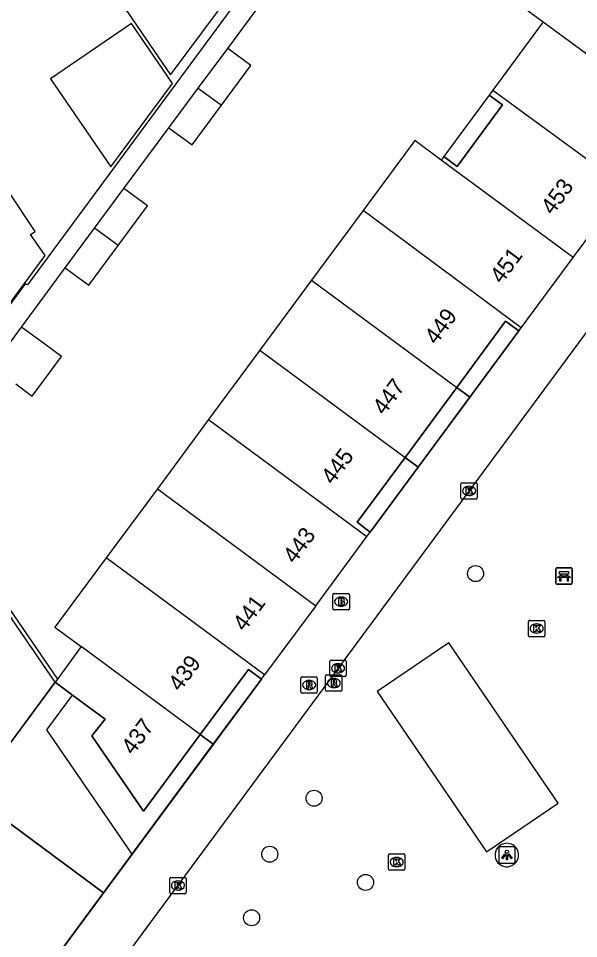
# Model space of a CAD drawing. Extents: x 155275 to 156263, y 382654 to 383635.
# Drawn here: x 155771.6 to 155805.7, y 383268.4 to 383324.6 of the extents above; entities that cross this region are included whole.
import ezdxf

# ---------------------------------------------------------------- set-up
doc = ezdxf.new("R2010")
doc.units = 0
for name, color, linetype in [('IMGEO_Bank', 7, 'Continuous'), ('IMGEO_Boom', 7, 'Continuous'), ('IMGEO_Brandkraan', 7, 'Continuous'), ('IMGEO_Kolk', 7, 'Continuous'), ('IMGEO_Lichtpunt', 7, 'Continuous'), ('IMGEO_Muur', 7, 'Continuous'), ('IMGEO_Pand', 7, 'Continuous'), ('IMGEO_Pand_nummerreeks', 7, 'Continuous'), ('IMGEO_Pand_overbouw', 7, 'Continuous'), ('IMGEO_Rijbaan_lokaal_open', 7, 'Continuous'), ('IMGEO_Rioolput', 7, 'Continuous'), ('IMGEO_Voetpad_open', 7, 'Continuous')]:
    doc.layers.add(name, color=color, linetype=linetype)

msp = doc.modelspace()

# ---------------------------------------------------------------- linework, layer by layer
at = {"layer": 'IMGEO_Bank'}
for p, q in [((155804.349, 383290.13), (155804.349, 383290.971)), ((155804.349, 383290.971), (155804.349, 383290.13)), ((155804.424, 383291.055), (155805.265, 383291.055)), ((155805.265, 383291.055), (155804.424, 383291.055)), ((155805.349, 383290.98), (155805.349, 383290.139)), ((155805.349, 383290.139), (155805.349, 383290.98)), ((155805.046, 383290.453), (155804.653, 383290.453)), ((155804.658, 383290.561), (155804.658, 383290.667)), ((155804.702, 383290.667), (155804.702, 383290.561)), ((155804.99, 383290.673), (155804.708, 383290.673)), ((155804.708, 383290.555), (155804.99, 383290.555)), ((155804.996, 383290.561), (155804.996, 383290.667)), ((155805.04, 383290.667), (155805.04, 383290.561)), ((155805.274, 383290.055), (155804.433, 383290.055)), ((155804.433, 383290.055), (155805.274, 383290.055))]:
    msp.add_line(p, q, dxfattribs=at)
for points in [[(155804.652, 383290.673), (155804.566, 383290.673), (155804.566, 383290.834), (155805.129, 383290.834), (155805.129, 383290.673), (155805.046, 383290.673)], [(155804.596, 383290.453), (155804.454, 383290.453), (155804.566, 383290.555), (155804.652, 383290.555)], [(155804.646, 383290.446), (155804.646, 383290.239), (155804.603, 383290.239), (155804.603, 383290.446)], [(155805.046, 383290.555), (155805.129, 383290.555), (155805.241, 383290.453), (155805.102, 383290.453)], [(155805.096, 383290.446), (155805.096, 383290.239), (155805.052, 383290.239), (155805.052, 383290.446)]]:
    msp.add_lwpolyline(points, dxfattribs=at)
for centre, radius, start, end in [((155804.427, 383290.977), 0.0779, 92.4484, 184.2845), ((155804.427, 383290.977), 0.0779, 92.4484, 184.2845), ((155805.271, 383290.977), 0.0779, 2.4484, 94.2845), ((155805.271, 383290.977), 0.0779, 2.4484, 94.2845), ((155804.596, 383290.446), 0.00671, 2.8957, 87.1043), ((155804.653, 383290.446), 0.00671, 92.8957, 177.1043), ((155804.651, 383290.666), 0.00671, 2.8957, 87.1043), ((155804.651, 383290.562), 0.00671, 272.8957, 357.1043), ((155804.708, 383290.666), 0.00671, 92.8957, 177.1043), ((155804.708, 383290.562), 0.00671, 182.8957, 267.1043), ((155804.99, 383290.666), 0.00671, 2.8957, 87.1043), ((155804.99, 383290.562), 0.00671, 272.8957, 357.1043), ((155805.047, 383290.666), 0.00671, 92.8957, 177.1043), ((155805.047, 383290.562), 0.00671, 182.8957, 267.1043), ((155805.045, 383290.446), 0.00671, 2.8957, 87.1043), ((155805.102, 383290.446), 0.00671, 92.8957, 177.1043), ((155804.427, 383290.133), 0.0779, 182.4484, 274.2845), ((155804.427, 383290.133), 0.0779, 182.4484, 274.2845), ((155805.271, 383290.133), 0.0779, 272.4484, 4.2845), ((155805.271, 383290.133), 0.0779, 272.4484, 4.2845)]:
    msp.add_arc(centre, radius, start, end, dxfattribs=at)
at = {"layer": 'IMGEO_Boom'}
for centre in [(155799.459, 383290.696), (155789.62, 383277), (155786.919, 383273.583), (155792.753, 383271.865), (155785.813, 383269.709)]:
    msp.add_circle(centre, 0.489, dxfattribs=at)
at = {"layer": 'IMGEO_Brandkraan'}
for p, q in [((155790.768, 383288.56), (155790.768, 383289.412)), ((155790.843, 383289.486), (155791.695, 383289.486)), ((155791.256, 383289.266), (155791.281, 383289.266)), ((155791.769, 383289.412), (155791.769, 383288.56)), ((155791.695, 383288.486), (155790.843, 383288.486)), ((155791.279, 383288.706), (155791.254, 383288.706))]:
    msp.add_line(p, q, dxfattribs=at)
for points in [[(155790.768, 383288.56), (155790.768, 383289.412)], [(155790.843, 383289.486), (155791.695, 383289.486)], [(155791.116, 383289.186), (155791.116, 383288.786), (155791.329, 383288.786)], [(155791.347, 383289.186), (155791.116, 383289.186)], [(155791.295, 383289.105), (155791.241, 383289.105), (155791.241, 383289.029)], [(155791.769, 383289.412), (155791.769, 383288.56)], [(155791.695, 383288.486), (155790.843, 383288.486)], [(155791.241, 383289.029), (155791.294, 383289.029)], [(155791.303, 383288.953), (155791.241, 383288.953), (155791.241, 383288.872)], [(155791.241, 383288.872), (155791.303, 383288.872)]]:
    msp.add_lwpolyline(points, dxfattribs=at)
for centre, radius, start, end in [((155790.845, 383289.41), 0.0765, 91.552, 178.448), ((155790.845, 383289.41), 0.0765, 91.552, 178.448), ((155791.296, 383289.067), 0.0379, 267.8285, 90.9355), ((155791.351, 383289.041), 0.145, 59.4692, 91.5367), ((155791.376, 383289.088), 0.0922, 285.5137, 58.1501), ((155791.693, 383289.41), 0.0765, 1.552, 88.448), ((155791.693, 383289.41), 0.0765, 1.552, 88.448), ((155790.845, 383288.562), 0.0765, 181.552, 268.448), ((155790.845, 383288.562), 0.0765, 181.552, 268.448), ((155791.304, 383288.912), 0.0404, 269.8759, 90.5077), ((155791.335, 383289.037), 0.251, 268.6676, 293.5347), ((155791.381, 383288.896), 0.105, 301.3115, 78.989), ((155791.693, 383288.562), 0.0765, 271.552, 358.448), ((155791.693, 383288.562), 0.0765, 271.552, 358.448)]:
    msp.add_arc(centre, radius, start, end, dxfattribs=at)
for centre, major_axis, ratio, start_param, end_param in [((155791.255, 383288.986), (-0.387, 0.002), 0.722429, 4.712389, 7.853982), ((155791.28, 383288.986), (-0.39, 0.002), 0.717154, 1.570796, 4.712389)]:
    msp.add_ellipse(centre, major_axis=major_axis, ratio=ratio, start_param=start_param, end_param=end_param, dxfattribs=at)
at = {"layer": 'IMGEO_Kolk'}
for p, q in [((155798.564, 383295.315), (155798.564, 383296.167)), ((155798.639, 383296.241), (155799.491, 383296.241)), ((155799.052, 383296.021), (155799.077, 383296.021)), ((155799.565, 383296.167), (155799.565, 383295.315)), ((155799.491, 383295.241), (155798.639, 383295.241)), ((155799.075, 383295.461), (155799.05, 383295.461)), ((155802.681, 383286.922), (155802.681, 383287.774)), ((155802.756, 383287.848), (155803.608, 383287.848)), ((155803.169, 383287.628), (155803.194, 383287.628)), ((155803.682, 383287.774), (155803.682, 383286.922)), ((155803.608, 383286.848), (155802.756, 383286.848)), ((155803.192, 383287.068), (155803.167, 383287.068)), ((155790.579, 383284.499), (155790.579, 383285.351)), ((155790.654, 383285.425), (155791.506, 383285.425)), ((155791.067, 383285.205), (155791.092, 383285.205)), ((155791.58, 383285.351), (155791.58, 383284.499)), ((155791.09, 383284.645), (155791.065, 383284.645)), ((155791.506, 383284.425), (155790.654, 383284.425)), ((155794.153, 383272.681), (155794.153, 383273.533)), ((155794.228, 383273.607), (155795.08, 383273.607)), ((155794.641, 383273.387), (155794.666, 383273.387)), ((155795.154, 383273.533), (155795.154, 383272.681)), ((155794.664, 383272.827), (155794.639, 383272.827)), ((155795.08, 383272.607), (155794.228, 383272.607)), ((155780.824, 383271.247), (155780.824, 383272.099)), ((155780.899, 383272.173), (155781.751, 383272.173)), ((155781.312, 383271.953), (155781.337, 383271.953)), ((155781.825, 383272.099), (155781.825, 383271.247)), ((155781.751, 383271.173), (155780.899, 383271.173)), ((155781.335, 383271.393), (155781.31, 383271.393))]:
    msp.add_line(p, q, dxfattribs=at)
for points in [[(155798.564, 383295.315), (155798.564, 383296.167)], [(155798.639, 383296.241), (155799.491, 383296.241)], [(155798.885, 383295.941), (155799.008, 383295.941), (155799.008, 383295.79), (155799.138, 383295.941), (155799.302, 383295.941), (155799.156, 383295.79), (155799.309, 383295.541), (155799.157, 383295.541), (155799.072, 383295.705), (155799.008, 383295.638), (155799.008, 383295.541), (155798.885, 383295.541), (155798.885, 383295.941)], [(155799.565, 383296.167), (155799.565, 383295.315)], [(155799.491, 383295.241), (155798.639, 383295.241)], [(155802.681, 383286.922), (155802.681, 383287.774)], [(155802.756, 383287.848), (155803.608, 383287.848)], [(155803.002, 383287.548), (155803.125, 383287.548), (155803.125, 383287.397), (155803.255, 383287.548), (155803.419, 383287.548), (155803.273, 383287.397), (155803.426, 383287.148), (155803.274, 383287.148), (155803.189, 383287.312), (155803.125, 383287.245), (155803.125, 383287.148), (155803.002, 383287.148), (155803.002, 383287.548)], [(155803.682, 383287.774), (155803.682, 383286.922)], [(155803.608, 383286.848), (155802.756, 383286.848)], [(155790.579, 383284.499), (155790.579, 383285.351)], [(155790.654, 383285.425), (155791.506, 383285.425)], [(155790.9, 383285.125), (155791.023, 383285.125), (155791.023, 383284.974), (155791.153, 383285.125), (155791.317, 383285.125), (155791.171, 383284.974), (155791.324, 383284.725), (155791.172, 383284.725), (155791.087, 383284.889), (155791.023, 383284.822), (155791.023, 383284.725), (155790.9, 383284.725), (155790.9, 383285.125)], [(155791.58, 383285.351), (155791.58, 383284.499)], [(155791.506, 383284.425), (155790.654, 383284.425)], [(155794.153, 383272.681), (155794.153, 383273.533)], [(155794.228, 383273.607), (155795.08, 383273.607)], [(155795.154, 383273.533), (155795.154, 383272.681)], [(155794.474, 383273.307), (155794.597, 383273.307), (155794.597, 383273.156), (155794.727, 383273.307), (155794.891, 383273.307), (155794.745, 383273.156), (155794.898, 383272.907), (155794.746, 383272.907), (155794.661, 383273.071), (155794.597, 383273.004), (155794.597, 383272.907), (155794.474, 383272.907), (155794.474, 383273.307)], [(155795.08, 383272.607), (155794.228, 383272.607)], [(155780.824, 383271.247), (155780.824, 383272.099)], [(155780.899, 383272.173), (155781.751, 383272.173)], [(155781.145, 383271.873), (155781.268, 383271.873), (155781.268, 383271.722), (155781.398, 383271.873), (155781.562, 383271.873), (155781.416, 383271.722), (155781.569, 383271.473), (155781.417, 383271.473), (155781.332, 383271.637), (155781.268, 383271.57), (155781.268, 383271.473), (155781.145, 383271.473), (155781.145, 383271.873)], [(155781.825, 383272.099), (155781.825, 383271.247)], [(155781.751, 383271.173), (155780.899, 383271.173)]]:
    msp.add_lwpolyline(points, dxfattribs=at)
for centre, start, end in [((155798.641, 383296.165), 91.552, 178.448), ((155798.641, 383296.165), 91.552, 178.448), ((155799.489, 383296.165), 1.552, 88.448), ((155799.489, 383296.165), 1.552, 88.448), ((155798.641, 383295.317), 181.552, 268.448), ((155798.641, 383295.317), 181.552, 268.448), ((155799.489, 383295.317), 271.552, 358.448), ((155799.489, 383295.317), 271.552, 358.448), ((155802.758, 383287.772), 91.552, 178.448), ((155802.758, 383287.772), 91.552, 178.448), ((155803.606, 383287.772), 1.552, 88.448), ((155803.606, 383287.772), 1.552, 88.448), ((155802.758, 383286.924), 181.552, 268.448), ((155802.758, 383286.924), 181.552, 268.448), ((155803.606, 383286.924), 271.552, 358.448), ((155803.606, 383286.924), 271.552, 358.448), ((155790.656, 383285.349), 91.552, 178.448), ((155790.656, 383285.349), 91.552, 178.448), ((155791.504, 383285.349), 1.552, 88.448), ((155791.504, 383285.349), 1.552, 88.448), ((155790.656, 383284.501), 181.552, 268.448), ((155790.656, 383284.501), 181.552, 268.448), ((155791.504, 383284.501), 271.552, 358.448), ((155791.504, 383284.501), 271.552, 358.448), ((155794.23, 383273.531), 91.552, 178.448), ((155794.23, 383273.531), 91.552, 178.448), ((155795.078, 383273.531), 1.552, 88.448), ((155795.078, 383273.531), 1.552, 88.448), ((155794.23, 383272.683), 181.552, 268.448), ((155794.23, 383272.683), 181.552, 268.448), ((155795.078, 383272.683), 271.552, 358.448), ((155795.078, 383272.683), 271.552, 358.448), ((155780.901, 383272.097), 91.552, 178.448), ((155780.901, 383272.097), 91.552, 178.448), ((155781.749, 383272.097), 1.552, 88.448), ((155781.749, 383272.097), 1.552, 88.448), ((155780.901, 383271.249), 181.552, 268.448), ((155780.901, 383271.249), 181.552, 268.448), ((155781.749, 383271.249), 271.552, 358.448), ((155781.749, 383271.249), 271.552, 358.448)]:
    msp.add_arc(centre, 0.0765, start, end, dxfattribs=at)
for centre, major_axis, ratio, start_param, end_param in [((155799.051, 383295.741), (-0.387, 0.002), 0.722429, 4.712389, 7.853982), ((155799.076, 383295.741), (-0.39, 0.002), 0.717154, 1.570796, 4.712389), ((155803.168, 383287.348), (-0.387, 0.002), 0.722429, 4.712389, 7.853982), ((155803.193, 383287.348), (-0.39, 0.002), 0.717154, 1.570796, 4.712389), ((155791.066, 383284.925), (-0.387, 0.002), 0.722429, 4.712389, 7.853982), ((155791.091, 383284.925), (-0.39, 0.002), 0.717154, 1.570796, 4.712389), ((155794.64, 383273.107), (-0.387, 0.002), 0.722429, 4.712389, 7.853982), ((155794.665, 383273.107), (-0.39, 0.002), 0.717154, 1.570796, 4.712389), ((155781.311, 383271.673), (-0.387, 0.002), 0.722429, 4.712389, 7.853982), ((155781.336, 383271.673), (-0.39, 0.002), 0.717154, 1.570796, 4.712389)]:
    msp.add_ellipse(centre, major_axis=major_axis, ratio=ratio, start_param=start_param, end_param=end_param, dxfattribs=at)
at = {"layer": 'IMGEO_Lichtpunt'}
for p, q in [((155800.871, 383273.939), (155800.871, 383273.132)), ((155800.871, 383273.939), (155800.871, 383273.132)), ((155801.773, 383274.034), (155800.965, 383274.034)), ((155801.773, 383274.034), (155800.965, 383274.034)), ((155801.867, 383273.132), (155801.867, 383273.939)), ((155801.867, 383273.132), (155801.867, 383273.939)), ((155800.965, 383273.038), (155801.773, 383273.038)), ((155800.965, 383273.038), (155801.773, 383273.038))]:
    msp.add_line(p, q, dxfattribs=at)
for points in [[(155801.245, 383273.603), (155801.284, 383273.575), (155801.096, 383273.313), (155801.058, 383273.34), (155801.245, 383273.603)], [(155801.347, 383273.555), (155801.394, 383273.555), (155801.394, 383273.233), (155801.347, 383273.233), (155801.347, 383273.555)], [(155801.457, 383273.575), (155801.495, 383273.602), (155801.682, 383273.34), (155801.643, 383273.312), (155801.457, 383273.575)]]:
    msp.add_lwpolyline(points, dxfattribs=at)
msp.add_circle((155801.37, 383273.737), 0.0994, dxfattribs=at)
for centre, start, end in [((155800.965, 383273.939), 90, 180), ((155800.965, 383273.939), 90, 180), ((155801.773, 383273.939), 0, 90), ((155801.773, 383273.939), 0, 90), ((155800.965, 383273.132), 180, 270), ((155800.965, 383273.132), 180, 270), ((155801.773, 383273.132), 270, 0), ((155801.773, 383273.132), 270, 360)]:
    msp.add_arc(centre, 0.0946, start, end, dxfattribs=at)
at = {"layer": 'IMGEO_Muur'}
for points in [[(155773.847, 383284.078), (155766.213, 383295.227)], [(155766.346, 383295.405), (155773.979, 383284.258)]]:
    msp.add_lwpolyline(points, dxfattribs=at)
at = {"layer": 'IMGEO_Pand'}
for points in [[(155806.716, 383328.599), (155805.114, 383329.78), (155801.982, 383325.533), (155803.581, 383324.349)], [(155781.002, 383320.579), (155778.5, 383324.24), (155773.56, 383320.879), (155777.229, 383315.499), (155781.002, 383320.579)], [(155803.581, 383324.349), (155800.509, 383320.186)], [(155803.581, 383324.349), (155810.843, 383319.005)], [(155782.566, 383320.31), (155784.362, 383322.728)], [(155783.979, 383319.26), (155785.775, 383321.678), (155784.362, 383322.728)], [(155780.77, 383317.892), (155782.566, 383320.31)], [(155782.566, 383320.31), (155783.979, 383319.26)], [(155800.509, 383320.186), (155800.28, 383319.875), (155801.107, 383319.278), (155798.332, 383315.532), (155797.518, 383316.133), (155797.358, 383315.917)], [(155800.509, 383320.186), (155808.587, 383314.27)], [(155780.77, 383317.892), (155782.183, 383316.842), (155783.979, 383319.26)], [(155797.358, 383315.917), (155795.763, 383317.106), (155792.614, 383312.847)], [(155773.237, 383310.096), (155772.35, 383311.386), (155772.624, 383311.569), (155769.306, 383316.514), (155764.095, 383312.762), (155762.477, 383315.13), (155756.977, 383311.371), (155761.822, 383304.288), (155762.664, 383304.864), (155763.459, 383303.7), (155762.617, 383303.124), (155762.936, 383302.658), (155763.787, 383303.237), (155765.884, 383300.163), (155773.237, 383310.096)], [(155805.407, 383309.97), (155797.358, 383315.917)], [(155776.245, 383311.76), (155778.034, 383314.181)], [(155777.677, 383310.703), (155779.465, 383313.124), (155778.034, 383314.181)], [(155805.407, 383309.97), (155808.587, 383314.27)], [(155792.614, 383312.847), (155789.463, 383308.585)], [(155802.245, 383305.695), (155792.614, 383312.847)], [(155774.457, 383309.339), (155776.245, 383311.76)], [(155777.677, 383310.703), (155776.245, 383311.76)], [(155774.457, 383309.339), (155775.888, 383308.282), (155777.677, 383310.703)], [(155802.245, 383305.695), (155805.407, 383309.97)], [(155789.463, 383308.585), (155786.313, 383304.323)], [(155789.463, 383308.585), (155798.311, 383302.048)], [(155798.311, 383302.048), (155801.291, 383306.088), (155802.098, 383305.496)], [(155770.012, 383303.314), (155771.797, 383305.735)], [(155771.437, 383302.262), (155772.446, 383301.517), (155774.232, 383303.941), (155773.223, 383304.684), (155771.797, 383305.735)], [(155802.098, 383305.496), (155802.245, 383305.695)], [(155786.313, 383304.323), (155783.19, 383300.098)], [(155786.313, 383304.323), (155795.165, 383297.783)], [(155795.165, 383297.783), (155798.311, 383302.048)], [(155783.19, 383300.098), (155780.069, 383295.876)], [(155783.19, 383300.098), (155792.841, 383292.963)], [(155793.035, 383293.224), (155792.246, 383293.826), (155795.165, 383297.783)], [(155780.069, 383295.876), (155776.948, 383291.655)], [(155780.069, 383295.876), (155789.72, 383288.742)], [(155789.72, 383288.742), (155792.841, 383292.963)], [(155792.841, 383292.963), (155793.035, 383293.224)], [(155776.948, 383291.655), (155773.822, 383287.426), (155775.431, 383286.243)], [(155786.598, 383284.52), (155776.948, 383291.655)], [(155789.72, 383288.742), (155786.598, 383284.52)], [(155775.431, 383286.243), (155773.979, 383284.258)], [(155782.682, 383280.882), (155775.431, 383286.243)], [(155782.682, 383280.882), (155785.615, 383284.849), (155786.405, 383284.259)], [(155773.979, 383284.258), (155773.847, 383284.078)], [(155773.847, 383284.078), (155774.904, 383283.294)], [(155786.405, 383284.259), (155786.598, 383284.52)], [(155774.904, 383283.294), (155776.886, 383281.823), (155776.079, 383280.798), (155779.225, 383276.207), (155782.682, 383280.882)]]:
    msp.add_lwpolyline(points, dxfattribs=at)
at = {"layer": 'IMGEO_Pand_overbouw'}
for points in [[(155800.28, 383319.875), (155797.518, 383316.133), (155798.332, 383315.532), (155801.107, 383319.278)], [(155798.311, 383302.048), (155799.114, 383301.455), (155802.098, 383305.496), (155801.291, 383306.088)], [(155798.311, 383302.048), (155795.165, 383297.783), (155795.965, 383297.192), (155799.114, 383301.455)], [(155795.165, 383297.783), (155792.246, 383293.826), (155793.035, 383293.224), (155795.965, 383297.192)], [(155782.682, 383280.882), (155783.479, 383280.293), (155786.405, 383284.259), (155785.615, 383284.849)], [(155776.886, 383281.823), (155774.904, 383283.294), (155773.836, 383284.086), (155768.735, 383277.191), (155776.792, 383271.232), (155783.479, 383280.293), (155782.682, 383280.882), (155779.225, 383276.207), (155776.079, 383280.798)], [(155771.65, 383264.258), (155776.792, 383271.232), (155768.735, 383277.191), (155762.039, 383268.14), (155762.867, 383267.527), (155766.131, 383271.951), (155766.263, 383272.13), (155769.629, 383267.192), (155768.939, 383266.259)]]:
    msp.add_lwpolyline(points, close=True, dxfattribs=at)
at = {"layer": 'IMGEO_Rijbaan_lokaal_open'}
for points in [[(155817.087, 383320.059), (155811.131, 383312.082), (155798.256, 383294.644), (155789.533, 383282.828), (155777.762, 383266.885), (155770.477, 383257.018), (155750.942, 383230.559), (155753.136, 383227.355), (155767.095, 383206.967), (155771.224, 383200.936), (155773.915, 383197.049), (155790.895, 383199.943), (155792.328, 383200.159), (155792.43, 383196.787)], [(155797.829, 383286.482), (155793.468, 383283.515), (155800.125, 383273.728), (155804.486, 383276.694), (155797.829, 383286.482)]]:
    msp.add_lwpolyline(points, dxfattribs=at)
for centre, start, end in [((155801.361, 383273.534), 119.6358, 299.1671), ((155801.364, 383273.536), 298.8814, 119.9215)]:
    msp.add_arc(centre, 0.714, start, end, dxfattribs=at)
at = {"layer": 'IMGEO_Rioolput'}
for p, q in [((155788.815, 383283.479), (155788.815, 383284.331)), ((155788.89, 383284.405), (155789.742, 383284.405)), ((155789.303, 383284.185), (155789.328, 383284.185)), ((155789.816, 383284.331), (155789.816, 383283.479)), ((155790.316, 383283.598), (155790.316, 383284.45)), ((155790.391, 383284.524), (155791.243, 383284.524)), ((155790.804, 383284.304), (155790.829, 383284.304)), ((155791.317, 383284.45), (155791.317, 383283.598)), ((155789.326, 383283.625), (155789.301, 383283.625)), ((155791.243, 383283.524), (155790.391, 383283.524)), ((155790.827, 383283.744), (155790.802, 383283.744)), ((155789.742, 383283.405), (155788.89, 383283.405))]:
    msp.add_line(p, q, dxfattribs=at)
for points in [[(155788.815, 383283.479), (155788.815, 383284.331)], [(155788.89, 383284.405), (155789.742, 383284.405)], [(155789.404, 383284.103), (155789.152, 383284.105), (155789.152, 383283.705)], [(155789.33, 383284.024), (155789.276, 383284.024), (155789.276, 383283.943)], [(155789.816, 383284.331), (155789.816, 383283.479)], [(155790.316, 383283.598), (155790.316, 383284.45)], [(155790.391, 383284.524), (155791.243, 383284.524)], [(155790.905, 383284.222), (155790.653, 383284.224), (155790.653, 383283.824)], [(155790.653, 383283.824), (155790.777, 383283.824), (155790.777, 383283.986), (155790.788, 383283.986)], [(155790.831, 383284.143), (155790.777, 383284.143), (155790.777, 383284.062)], [(155790.777, 383284.062), (155790.829, 383284.062)], [(155791.317, 383284.45), (155791.317, 383283.598)], [(155789.152, 383283.705), (155789.276, 383283.705), (155789.276, 383283.867), (155789.287, 383283.867)], [(155789.276, 383283.943), (155789.328, 383283.943)], [(155789.334, 383283.838), (155789.405, 383283.705), (155789.545, 383283.705), (155789.48, 383283.831)], [(155791.243, 383283.524), (155790.391, 383283.524)], [(155790.835, 383283.957), (155790.906, 383283.824), (155791.046, 383283.824), (155790.981, 383283.95)], [(155789.742, 383283.405), (155788.89, 383283.405)]]:
    msp.add_lwpolyline(points, dxfattribs=at)
for centre, radius, start, end in [((155788.892, 383284.329), 0.0765, 91.552, 178.448), ((155788.892, 383284.329), 0.0765, 91.552, 178.448), ((155789.336, 383283.928), 0.0964, 77.0061, 93.1865), ((155789.35, 383283.985), 0.0378, 276.6634, 79.6772), ((155789.403, 383283.993), 0.109, 350.3612, 89.416), ((155789.74, 383284.329), 0.0765, 1.552, 88.448), ((155789.74, 383284.329), 0.0765, 1.552, 88.448), ((155790.393, 383284.448), 0.0765, 91.552, 178.448), ((155790.393, 383284.448), 0.0765, 91.552, 178.448), ((155790.787, 383283.933), 0.0533, 26.0293, 88.6989), ((155790.813, 383284.251), 0.19, 274.7715, 282.9687), ((155790.837, 383284.047), 0.0964, 77.0061, 93.1865), ((155790.851, 383284.104), 0.0378, 276.6634, 79.6772), ((155790.904, 383284.112), 0.109, 350.3612, 89.416), ((155790.902, 383284.112), 0.112, 277.5842, 350.9817), ((155790.886, 383283.897), 0.108, 29.5134, 73.7905), ((155791.241, 383284.448), 0.0765, 1.552, 88.448), ((155791.241, 383284.448), 0.0765, 1.552, 88.448), ((155788.892, 383283.481), 0.0765, 181.552, 268.448), ((155788.892, 383283.481), 0.0765, 181.552, 268.448), ((155789.286, 383283.814), 0.0533, 26.0293, 88.6989), ((155789.312, 383284.132), 0.19, 274.7715, 282.9687), ((155789.401, 383283.993), 0.112, 277.5842, 350.9817), ((155789.385, 383283.778), 0.108, 29.5134, 73.7905), ((155789.74, 383283.481), 0.0765, 271.552, 358.448), ((155789.74, 383283.481), 0.0765, 271.552, 358.448), ((155790.393, 383283.6), 0.0765, 181.552, 268.448), ((155790.393, 383283.6), 0.0765, 181.552, 268.448), ((155791.241, 383283.6), 0.0765, 271.552, 358.448), ((155791.241, 383283.6), 0.0765, 271.552, 358.448)]:
    msp.add_arc(centre, radius, start, end, dxfattribs=at)
for centre, major_axis, ratio, start_param, end_param in [((155789.302, 383283.905), (-0.387, 0.002), 0.722429, 4.712389, 7.853982), ((155789.327, 383283.905), (-0.39, 0.002), 0.717154, 1.570796, 4.712389), ((155790.803, 383284.024), (-0.387, 0.002), 0.722429, 4.712389, 7.853982), ((155790.828, 383284.024), (-0.39, 0.002), 0.717154, 1.570796, 4.712389)]:
    msp.add_ellipse(centre, major_axis=major_axis, ratio=ratio, start_param=start_param, end_param=end_param, dxfattribs=at)
at = {"layer": 'IMGEO_Voetpad_open'}
for points in [[(155748.624, 383368.233), (155780.862, 383321.113), (155784.569, 383326.097), (155785.094, 383326.809), (155753.833, 383372.536)], [(155804.41, 383349.86), (155805.536, 383351.381), (155804.469, 383352.147), (155772.167, 383308.3), (155772.022, 383308.374), (155765.785, 383299.873)], [(155784.362, 383322.728), (155787.013, 383326.328)], [(155778.034, 383314.181), (155780.77, 383317.892)], [(155771.797, 383305.735), (155774.457, 383309.339)], [(155802.098, 383305.496), (155793.035, 383293.224)], [(155765.677, 383272.995), (155773.847, 383284.078)], [(155786.405, 383284.259), (155778.526, 383273.579)], [(155778.526, 383273.579), (155773.337, 383281.178), (155774.904, 383283.294)], [(155778.526, 383273.579), (155772.869, 383265.909)]]:
    msp.add_lwpolyline(points, dxfattribs=at)

# ---------------------------------------------------------------- texts
at = {"layer": 'IMGEO_Pand_nummerreeks'}
for s, rotation, p in [('453', 53.5126, (155804.153, 383312.513)), ('451', 53.5126, (155801.048, 383308.314)), ('449', 53.5877, (155797.061, 383304.6)), ('447', 53.5437, (155793.895, 383300.306)), ('445', 53.5877, (155790.765, 383296.063)), ('443', 53.5256, (155788.436, 383291.245)), ('441', 53.5157, (155785.381, 383287.112)), ('439', 53.5198, (155781.445, 383283.447)), ('437', 53.5198, (155778.589, 383279.585))]:
    msp.add_text(s, height=1, rotation=rotation, dxfattribs=at).set_placement(p)

doc.saveas('drawing.dxf')
